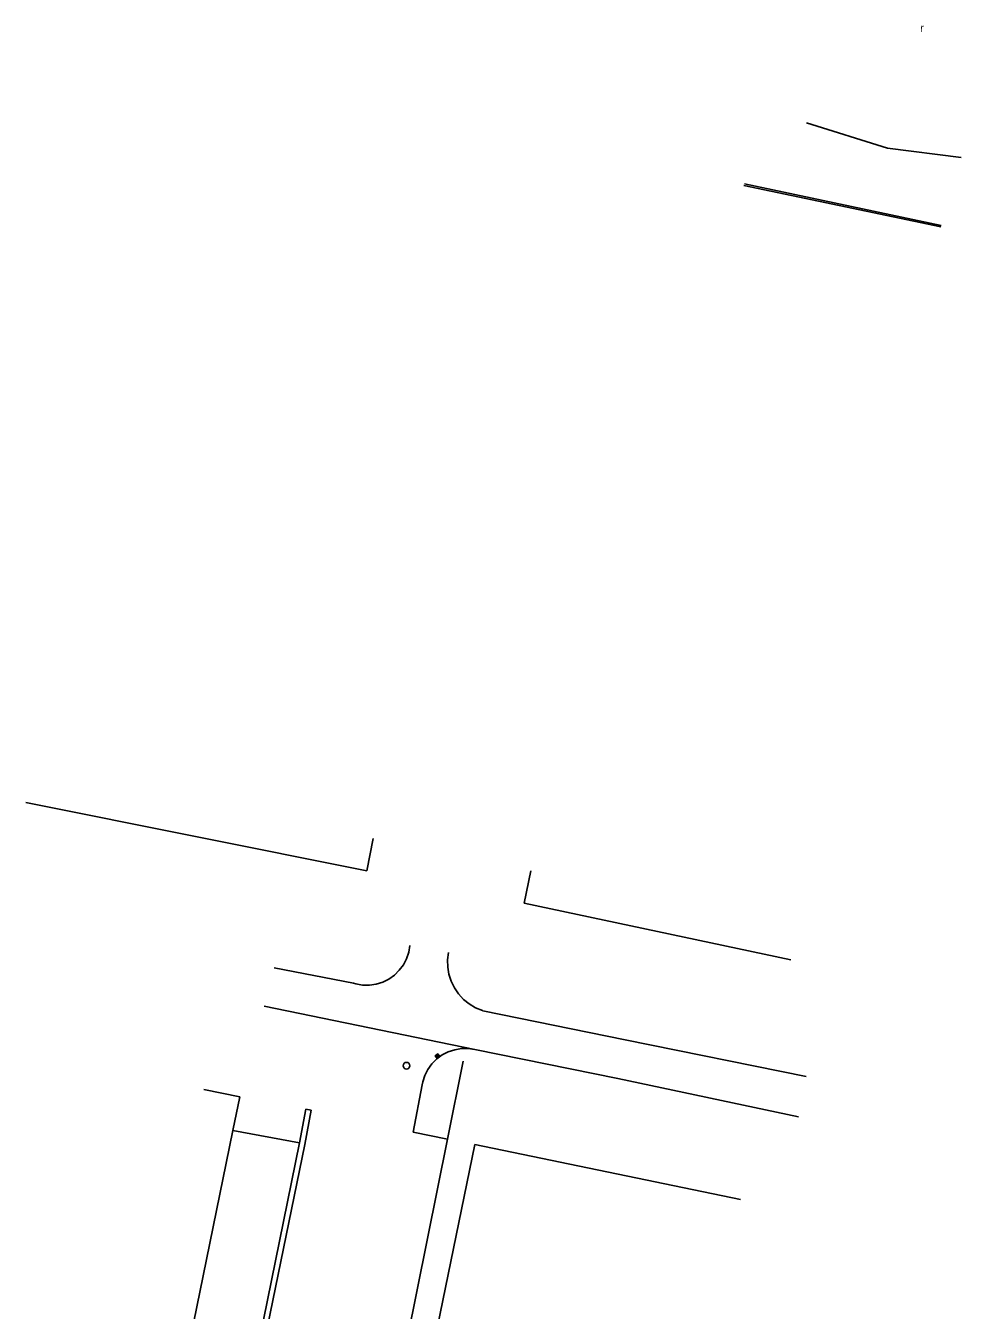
# Model space of a CAD drawing. Extents: x -540235 to -537963, y -1184915 to -1183660.
# Drawn here: x -538209.1 to -538068.9, y -1184491.1 to -1184298.5 of the extents above; entities that cross this region are included whole.
import ezdxf

# ---------------------------------------------------------------- set-up
doc = ezdxf.new("R2010")
doc.units = 0
for name, color, linetype in [('Vrstva 10', 7, 'Continuous'), ('Vrstva 23', 7, 'Continuous'), ('Vrstva 27', 7, 'Continuous'), ('Vrstva 36', 7, 'Continuous'), ('Vrstva 5', 7, 'Continuous'), ('Vrstva 7', 7, 'Continuous')]:
    doc.layers.add(name, color=color, linetype=linetype)

msp = doc.modelspace()

# ---------------------------------------------------------------- linework, layer by layer
at = {"layer": 'Vrstva 10'}
for p, q in [((-538171.84, -1184439.75), (-538159.98, -1184442.06)), ((-538141.76, -1184452.01), (-538173.37, -1184445.48)), ((-538119.25, -1184450.52), (-538140.55, -1184446.17)), ((-538092.12, -1184456.06), (-538119.25, -1184450.52)), ((-538120.36, -1184456.36), (-538141.76, -1184452.01)), ((-538149.67, -1184457.31), (-538151.02, -1184464.39)), ((-538093.24, -1184462.08), (-538120.36, -1184456.36)), ((-538168.04, -1184465.99), (-538167.08, -1184460.94)), ((-538167.25, -1184466.24), (-538166.28, -1184461.1)), ((-538166.28, -1184461.1), (-538167.08, -1184460.94)), ((-538168.04, -1184465.99), (-538178.043, -1184464.122)), ((-538151.02, -1184464.39), (-538145.86, -1184465.46)), ((-538174.47, -1184497.49), (-538168.04, -1184465.99)), ((-538173.71, -1184497.65), (-538167.25, -1184466.24)), ((-538155.17, -1184531.7), (-538141.79, -1184466.22)), ((-538141.79, -1184466.22), (-538101.967, -1184474.501))]:
    msp.add_line(p, q, dxfattribs=at)
for points in [[(-538151.5, -1184436.41), (-538151.675, -1184437.419), (-538152.005, -1184438.388), (-538152.482, -1184439.294), (-538153.094, -1184440.115), (-538153.826, -1184440.83), (-538154.66, -1184441.423), (-538155.577, -1184441.879), (-538156.553, -1184442.187), (-538157.566, -1184442.339)], [(-538145.72, -1184437.44), (-538145.857, -1184438.533), (-538145.835, -1184439.634), (-538145.653, -1184440.72), (-538145.316, -1184441.768), (-538144.831, -1184442.757), (-538144.208, -1184443.665), (-538143.461, -1184444.473), (-538142.604, -1184445.165), (-538141.656, -1184445.725)], [(-538157.566, -1184442.339), (-538158.589, -1184442.332), (-538159.6, -1184442.166), (-538159.98, -1184442.06)], [(-538141.656, -1184445.725), (-538140.637, -1184446.142), (-538140.55, -1184446.17)], [(-538141.76, -1184452.01), (-538142.768, -1184451.856), (-538143.788, -1184451.862), (-538144.794, -1184452.026), (-538145.763, -1184452.346), (-538146.669, -1184452.813), (-538147.492, -1184453.416), (-538148.21, -1184454.14), (-538148.806, -1184454.967), (-538149.266, -1184455.878)], [(-538149.266, -1184455.878), (-538149.578, -1184456.849), (-538149.67, -1184457.31)]]:
    msp.add_lwpolyline(points, dxfattribs=at)
at = {"layer": 'Vrstva 23'}
for p, q in [((-538092.04, -1184313.06), (-538079.94, -1184316.82)), ((-538079.94, -1184316.82), (-538068.86, -1184318.24))]:
    msp.add_line(p, q, dxfattribs=at)
at = {"layer": 'Vrstva 27'}
msp.add_line((-538147.585, -1184453.156), (-538147.185, -1184452.856), dxfattribs=at)
msp.add_lwpolyline([(-538147.435, -1184453.356), (-538147.035, -1184453.056), (-538147.335, -1184452.656), (-538147.735, -1184452.956)], close=True, dxfattribs=at)
msp.add_circle((-538152.02, -1184454.42), 0.5, dxfattribs=at)
at = {"layer": 'Vrstva 5'}
for p, q in [((-538209.09, -1184414.95), (-538157.98, -1184425.21)), ((-538157.98, -1184425.21), (-538156.989, -1184420.345)), ((-538134.39, -1184430.06), (-538133.399, -1184425.195)), ((-538094.411, -1184438.557), (-538134.39, -1184430.06)), ((-538177.01, -1184459.08), (-538182.383, -1184457.979)), ((-538178.043, -1184464.122), (-538177.01, -1184459.08)), ((-538189.06, -1184517.9), (-538178.043, -1184464.122))]:
    msp.add_line(p, q, dxfattribs=at)
at = {"layer": 'Vrstva 7'}
for p, q in [((-538101.43, -1184322.45), (-538071.93, -1184328.66)), ((-538071.88, -1184328.415), (-538101.379, -1184322.205)), ((-538143.497, -1184453.757), (-538145.86, -1184465.46)), ((-538145.86, -1184465.46), (-538152.56, -1184498.64))]:
    msp.add_line(p, q, dxfattribs=at)

# ---------------------------------------------------------------- texts
at = {"layer": 'Vrstva 36'}
msp.add_text('r', height=1.2, dxfattribs=at).set_placement((-538075.03, -1184299.413))

doc.saveas('drawing.dxf')
